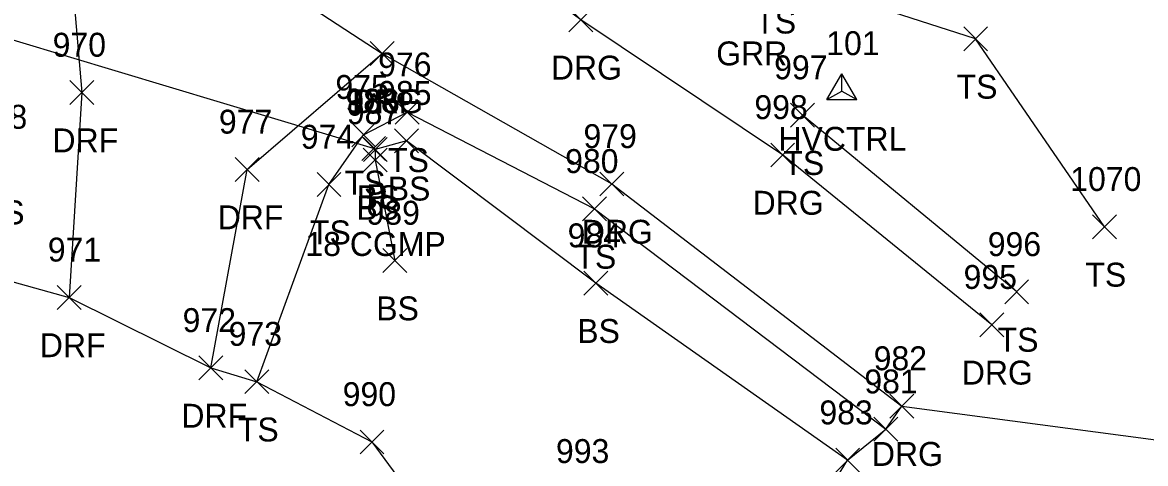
# Model space of a CAD drawing. Extents: x 1679360 to 1685861, y 903420 to 905946.
# Drawn here: x 1679736.4 to 1679830.3, y 903927 to 903963.9 of the extents above; entities that cross this region are included whole.
import ezdxf

# ---------------------------------------------------------------- set-up
doc = ezdxf.new("R2010")
doc.units = 0
for name, color, linetype in [('C_A', 7, 'Continuous'), ('C_I', 7, 'Continuous'), ('CPSM', 7, 'Continuous'), ('D_A', 7, 'Continuous'), ('D_C', 7, 'Continuous'), ('D_I', 7, 'Continuous'), ('D_TIC', 7, 'Continuous'), ('DCP', 7, 'Continuous'), ('L_A', 7, 'Continuous'), ('L_I', 7, 'Continuous'), ('L_TIC', 7, 'Continuous'), ('LELB', 7, 'Continuous'), ('LSOGP', 7, 'Continuous'), ('R_A', 7, 'Continuous'), ('R_I', 7, 'Continuous'), ('R_TIC', 7, 'Continuous'), ('RDF', 7, 'Continuous'), ('RDG', 7, 'Continuous')]:
    doc.layers.add(name, color=color, linetype=linetype)

msp = doc.modelspace()

# ---------------------------------------------------------------- linework, layer by layer
at = {"layer": 'CPSM'}
for p, q in [((1679803.703, 903957.418), (1679804.953, 903959.583)), ((1679806.203, 903957.418), (1679804.953, 903959.583)), ((1679804.954, 903958.139), (1679804.953, 903959.583)), ((1679803.703, 903957.418), (1679804.954, 903958.139)), ((1679804.954, 903958.139), (1679804.954, 903958.139)), ((1679804.954, 903958.139), (1679806.203, 903957.418)), ((1679803.703, 903957.418), (1679806.203, 903957.418))]:
    msp.add_line(p, q, dxfattribs=at)
at = {"layer": 'D_TIC'}
for points in [[(1679764.801, 903952.339), (1679766.801, 903954.339)], [(1679766.801, 903952.339), (1679764.801, 903954.339)]]:
    msp.add_lwpolyline(points, dxfattribs=at)
at = {"layer": 'DCP'}
msp.add_lwpolyline([(1679765.801, 903953.339), (1679727.373, 903964.869)], dxfattribs=at)
at = {"layer": 'L_TIC'}
for points in [[(1679815.139, 903961.498), (1679817.139, 903963.498)], [(1679817.139, 903961.498), (1679815.139, 903963.498)], [(1679767.595, 903955.359), (1679769.595, 903957.359)], [(1679769.595, 903955.359), (1679767.595, 903957.359)], [(1679800.652, 903955.118), (1679802.652, 903957.118)], [(1679802.652, 903955.118), (1679800.652, 903957.118)], [(1679763.964, 903953.476), (1679765.964, 903955.476)], [(1679765.964, 903953.476), (1679763.964, 903955.476)], [(1679764.94, 903952.251), (1679766.94, 903954.251)], [(1679766.94, 903952.251), (1679764.94, 903954.251)], [(1679767.537, 903952.976), (1679769.537, 903954.976)], [(1679769.537, 903952.976), (1679767.537, 903954.976)], [(1679764.917, 903951.365), (1679766.917, 903953.365)], [(1679766.917, 903951.365), (1679764.917, 903953.365)], [(1679761.066, 903949.311), (1679763.066, 903951.311)], [(1679763.066, 903949.311), (1679761.066, 903951.311)], [(1679783.262, 903947.278), (1679785.262, 903949.278)], [(1679785.262, 903947.278), (1679783.262, 903949.278)], [(1679825.909, 903945.775), (1679827.909, 903947.775)], [(1679827.909, 903945.775), (1679825.909, 903947.775)], [(1679766.574, 903942.956), (1679768.574, 903944.956)], [(1679768.574, 903942.956), (1679766.574, 903944.956)], [(1679783.383, 903941.064), (1679785.383, 903943.064)], [(1679785.383, 903941.064), (1679783.383, 903943.064)], [(1679818.571, 903940.331), (1679820.571, 903942.331)], [(1679820.571, 903940.331), (1679818.571, 903942.331)], [(1679755.035, 903932.825), (1679757.035, 903934.825)], [(1679757.035, 903932.825), (1679755.035, 903934.825)], [(1679807.627, 903928.843), (1679809.627, 903930.843)], [(1679809.627, 903928.843), (1679807.627, 903930.843)], [(1679764.659, 903927.78), (1679766.659, 903929.78)], [(1679766.659, 903927.78), (1679764.659, 903929.78)], [(1679804.438, 903926.254), (1679806.438, 903928.254)], [(1679806.438, 903926.254), (1679804.438, 903928.254)]]:
    msp.add_lwpolyline(points, dxfattribs=at)
at = {"layer": 'LELB'}
for points in [[(1679826.909, 903946.775), (1679816.139, 903962.498), (1679799.3, 903967.949), (1679786.9, 903972.592), (1679770.418, 903982.075), (1679752.253, 903992.328), (1679749.667, 904002.531), (1679749.546, 904012.229), (1679768.469, 904013.239), (1679790.366, 904010.321), (1679808.954, 904003.393), (1679828.407, 903995.686), (1679842.28, 903987.378), (1679854.89, 903981.602), (1679861.766, 903973.84), (1679868.316, 903960.054)], [(1679756.035, 903933.825), (1679762.066, 903950.311), (1679764.964, 903954.476), (1679768.595, 903956.359), (1679784.262, 903948.278), (1679808.627, 903929.843)], [(1679819.571, 903941.331), (1679801.652, 903956.118)], [(1679805.438, 903927.254), (1679784.383, 903942.064), (1679768.537, 903953.976), (1679765.94, 903953.251), (1679765.917, 903952.365), (1679767.574, 903943.956)]]:
    msp.add_lwpolyline(points, dxfattribs=at)
at = {"layer": 'LSOGP'}
msp.add_lwpolyline([(1679658.655, 903956.214), (1679681.247, 903951.787), (1679705.024, 903947.171), (1679724.722, 903944.324), (1679729.231, 903943.97), (1679740.349, 903940.875), (1679752.187, 903934.974), (1679756.035, 903933.825), (1679765.659, 903928.78), (1679788.577, 903897.601), (1679796.73, 903913.039), (1679805.438, 903927.254), (1679808.627, 903929.843), (1679809.974, 903931.781), (1679849.708, 903926.515)], dxfattribs=at)
at = {"layer": 'R_TIC'}
for points in [[(1679782.134, 903963.096), (1679784.134, 903965.096)], [(1679784.134, 903963.096), (1679782.134, 903965.096)], [(1679765.509, 903960.278), (1679767.509, 903962.278)], [(1679767.509, 903960.278), (1679765.509, 903962.278)], [(1679765.509, 903960.278), (1679767.509, 903962.278)], [(1679767.509, 903960.278), (1679765.509, 903962.278)], [(1679740.406, 903957.01), (1679742.406, 903959.01)], [(1679742.406, 903957.01), (1679740.406, 903959.01)], [(1679799, 903951.789), (1679801, 903953.789)], [(1679801, 903951.789), (1679799, 903953.789)], [(1679754.223, 903950.575), (1679756.223, 903952.575)], [(1679756.223, 903950.575), (1679754.223, 903952.575)], [(1679784.717, 903949.364), (1679786.717, 903951.364)], [(1679786.717, 903949.364), (1679784.717, 903951.364)], [(1679739.349, 903939.875), (1679741.349, 903941.875)], [(1679741.349, 903939.875), (1679739.349, 903941.875)], [(1679816.493, 903937.584), (1679818.493, 903939.584)], [(1679818.493, 903937.584), (1679816.493, 903939.584)], [(1679751.187, 903933.974), (1679753.187, 903935.974)], [(1679753.187, 903933.974), (1679751.187, 903935.974)], [(1679808.974, 903930.781), (1679810.974, 903932.781)], [(1679810.974, 903930.781), (1679808.974, 903932.781)]]:
    msp.add_lwpolyline(points, dxfattribs=at)
at = {"layer": 'RDF'}
for points in [[(1679739.608, 903978.837), (1679741.406, 903958.01), (1679740.349, 903940.875)], [(1679752.187, 903934.974), (1679755.223, 903951.575), (1679766.509, 903961.278)]]:
    msp.add_lwpolyline(points, dxfattribs=at)
at = {"layer": 'RDG'}
for points in [[(1679661.16, 904024.917), (1679683.887, 904015.944), (1679697.931, 904008.669), (1679719.81, 903993.908), (1679739.608, 903978.837), (1679766.509, 903961.278), (1679785.717, 903950.364), (1679809.974, 903931.781)], [(1679817.493, 903938.584), (1679800, 903952.789), (1679783.134, 903964.096), (1679760.777, 903980.639), (1679747.854, 903990.18), (1679739.743, 904001.37), (1679737.475, 904014.621)]]:
    msp.add_lwpolyline(points, dxfattribs=at)

# ---------------------------------------------------------------- texts
at = {"layer": 'C_A'}
msp.add_text('HVCTRL', height=2, dxfattribs=at).set_placement((1679799.647, 903953.139))
at = {"layer": 'C_I'}
msp.add_text('101', height=2, dxfattribs=at).set_placement((1679803.647, 903961.139))
at = {"layer": 'D_A'}
msp.add_text('P', height=2, dxfattribs=at).set_placement((1679765.179, 903948.339))
at = {"layer": 'D_C'}
msp.add_text('18 CGMP', height=2, dxfattribs=at).set_placement((1679760.092, 903944.339))
at = {"layer": 'D_I'}
msp.add_text('988', height=2, dxfattribs=at).set_placement((1679763.439, 903956.339))
at = {"layer": 'L_A'}
for s, p in [('TS', (1679797.709, 903962.949)), ('TS', (1679814.549, 903957.498)), ('TS', (1679767.004, 903951.359)), ('TS', (1679800.061, 903951.118)), ('TS', (1679763.373, 903949.476)), ('BS', (1679766.978, 903948.976)), ('BS', (1679764.381, 903948.251)), ('TS', (1679733.189, 903946.983)), ('BS', (1679764.357, 903947.365)), ('TS', (1679760.476, 903945.311)), ('TS', (1679782.671, 903943.278)), ('TS', (1679825.319, 903941.775)), ('BS', (1679766.015, 903938.956)), ('BS', (1679782.824, 903937.064)), ('TS', (1679817.98, 903936.331)), ('TS', (1679754.444, 903928.825))]:
    msp.add_text(s, height=2, dxfattribs=at).set_placement(p)
at = {"layer": 'L_I'}
for s, p in [('976', (1679766.177, 903959.359)), ('997', (1679799.29, 903959.118)), ('975', (1679762.602, 903957.476)), ('985', (1679766.175, 903956.976)), ('986', (1679763.523, 903956.251)), ('968', (1679732.37, 903954.983)), ('987', (1679763.554, 903955.365)), ('974', (1679759.704, 903953.311)), ('980', (1679781.813, 903951.278)), ('1070', (1679824.051, 903949.775)), ('989', (1679765.204, 903946.956)), ('984', (1679782.02, 903945.064)), ('996', (1679817.154, 903944.331)), ('973', (1679753.672, 903936.825)), ('981', (1679806.832, 903932.843)), ('990', (1679763.21, 903931.78)), ('983', (1679803.076, 903930.254)), ('993', (1679781.045, 903927.021))]:
    msp.add_text(s, height=2, dxfattribs=at).set_placement(p)
at = {"layer": 'R_A'}
for s, p in [('GRR', (1679794.447, 903960.284)), ('DRG', (1679780.622, 903959.096)), ('DRG', (1679763.998, 903956.278)), ('DRF', (1679764.045, 903956.278)), ('DRF', (1679738.941, 903953.01)), ('DRG', (1679797.488, 903947.789)), ('DRF', (1679752.759, 903946.575)), ('DRG', (1679783.206, 903945.364)), ('DRF', (1679737.885, 903935.875)), ('DRG', (1679814.981, 903933.584)), ('DRF', (1679749.723, 903929.974)), ('DRG', (1679807.462, 903926.781))]:
    msp.add_text(s, height=2, dxfattribs=at).set_placement(p)
at = {"layer": 'R_I'}
for s, p in [('970', (1679738.957, 903961.01)), ('998', (1679797.638, 903955.789)), ('977', (1679752.861, 903954.575)), ('979', (1679783.347, 903953.364)), ('971', (1679738.554, 903943.875)), ('995', (1679815.131, 903941.584)), ('972', (1679749.825, 903937.974)), ('982', (1679807.611, 903934.781))]:
    msp.add_text(s, height=2, dxfattribs=at).set_placement(p)

doc.saveas('drawing.dxf')
